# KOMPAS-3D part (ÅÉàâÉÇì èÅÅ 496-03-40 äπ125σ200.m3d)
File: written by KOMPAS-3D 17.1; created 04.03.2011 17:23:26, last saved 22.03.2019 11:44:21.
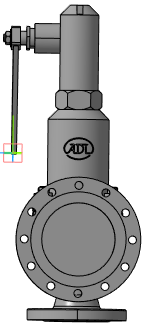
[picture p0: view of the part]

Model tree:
1. Плоскость XY
2. Плоскость ZX
3. Плоскость ZY
4. Ось X
5. Ось Y
6. Ось Z
7. Начало координат
8. Операция без истории:2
